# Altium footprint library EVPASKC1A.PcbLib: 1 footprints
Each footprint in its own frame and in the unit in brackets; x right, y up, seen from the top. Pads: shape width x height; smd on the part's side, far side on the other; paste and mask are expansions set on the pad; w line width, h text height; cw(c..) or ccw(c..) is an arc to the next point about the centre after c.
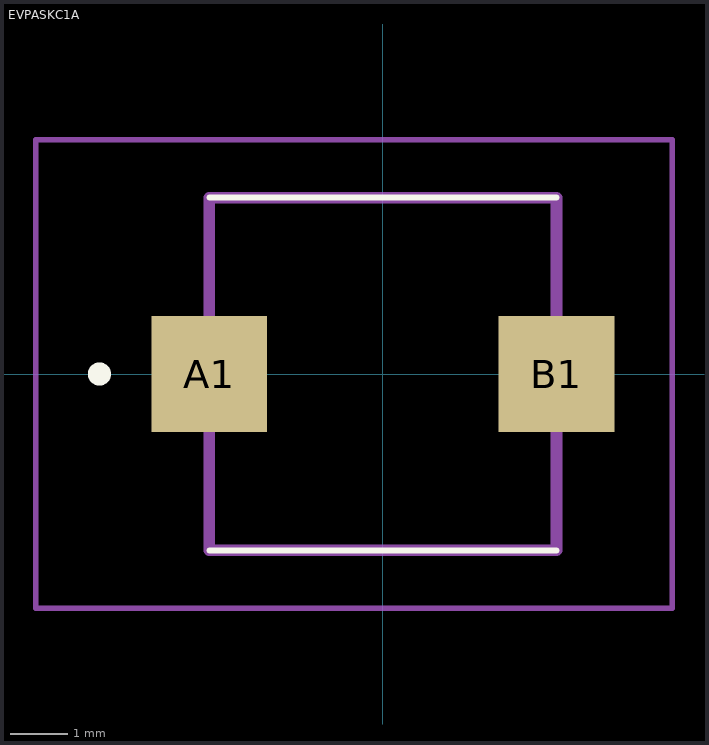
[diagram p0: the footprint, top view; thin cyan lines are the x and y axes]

## EVPASKC1A [mm]
pads (2):
  rect 2x2 smd: A1(-3,0) B1(3,0)
Top Overlay:
  lines w0.1: -3,-3.05 3,-3.05 ; -3,3.05 3,3.05
  lines w0.2: -5,0 -5,0 ; -5,0 ccw(c-4.9,0) -4.8,0 ; -5,0 cw(c-4.9,0) -4.8,0 ; -4.8,0 -4.8,0
Mechanical 15:
  lines w0.2: -3,-3.05 3,-3.05 3,3.05 -3,3.05 -3,-3.05
Mechanical 20:
  lines w0.1: -6,-4.05 5,-4.05 5,4.05 -6,4.05 -6,-4.05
